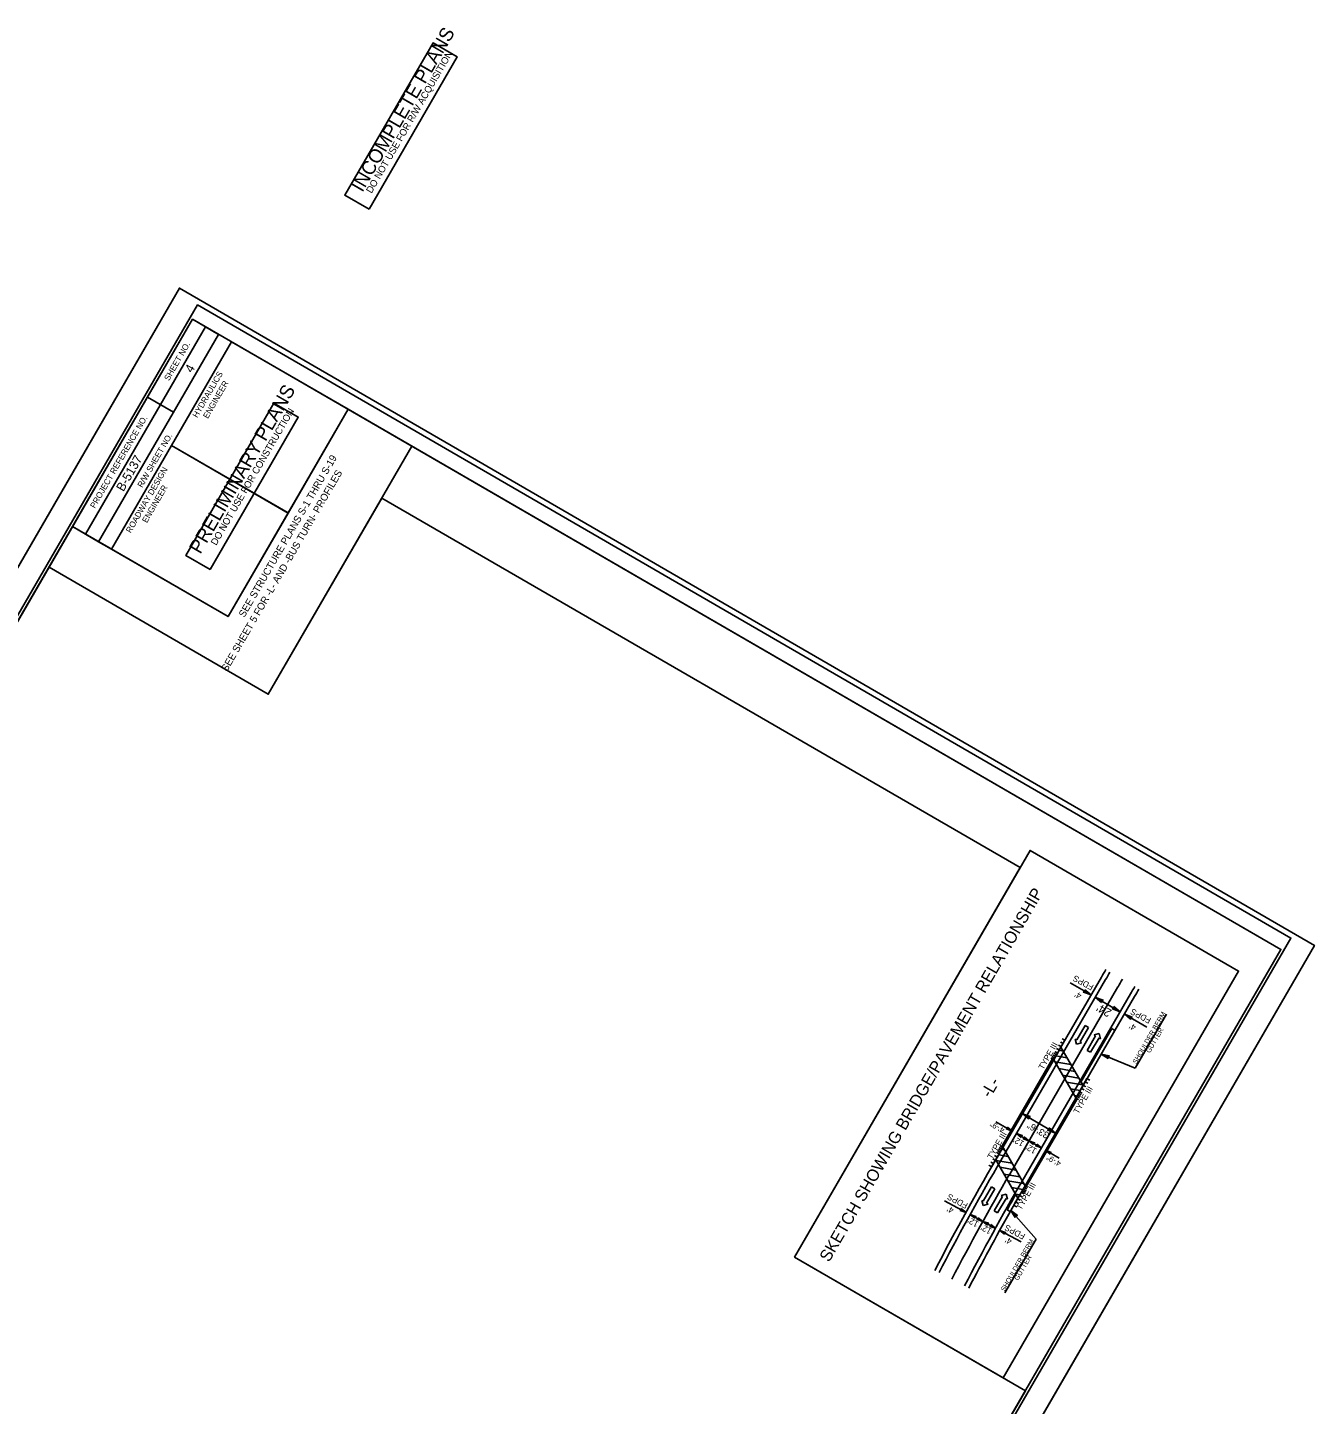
# Model space of a CAD drawing. Extents: x 1652765 to 1654556, y 596901 to 599124.
# Drawn here: x 1653481 to 1654556, y 597974 to 599124 of the extents above; entities that cross this region are included whole.
import ezdxf

# ---------------------------------------------------------------- set-up
doc = ezdxf.new("R2010")
doc.units = 0
for name, color, linetype in [('Prop Approach Slab', 7, 'Continuous'), ('Prop Approach Slab Hatching', 7, 'Continuous'), ('Prop Conc Shoulder Berm Gutter', 7, 'Continuous'), ('Prop Dimension Text', 7, 'Continuous'), ('Prop EOT', 7, 'Continuous'), ('Prop Horizontal Alignment', 7, 'Continuous'), ('Prop Horizontal Alignment Tick Label', 7, 'Continuous'), ('Prop Horizontal Alignment Tick Large', 7, 'Continuous'), ('Prop Horizontal Alignment Tick Small', 7, 'Continuous'), ('Prop Lane Arrow CELL', 7, 'Continuous'), ('Prop Paved Shoulder', 7, 'Continuous'), ('Prop Roadway Bridge', 7, 'Continuous'), ('Prop Structure Anchor Unit CELL', 7, 'Continuous'), ('Prop Terminator CELL', 7, 'Continuous'), ('Sheet Cutting Line CELL', 7, 'Continuous'), ('Sheet Plan Layout CELL', 7, 'Continuous'), ('Sheet Plot Border Inside CELL', 7, 'Continuous'), ('Sheet Sticker Incomplete CELL', 7, 'Continuous'), ('Sheet Sticker Preliminary CELL', 7, 'Continuous')]:
    doc.layers.add(name, color=color, linetype=linetype)

msp = doc.modelspace()

# ---------------------------------------------------------------- linework, layer by layer
at = {"layer": 'Prop Approach Slab'}
for p, q in [((1654338.2, 598262), (1654344.2, 598272.4)), ((1654362.7, 598240.4), (1654344.2, 598272.4)), ((1654356.6, 598230), (1654362.7, 598240.4)), ((1654289.8, 598178.5), (1654295.8, 598188.8)), ((1654289.8, 598178.5), (1654308.3, 598146.4)), ((1654308.3, 598146.4), (1654314.3, 598156.8))]:
    msp.add_line(p, q, dxfattribs=at)
at = {"layer": 'Prop Approach Slab Hatching'}
for p, q in [((1654342.7, 598269.9), (1654346, 598269.3)), ((1654339.2, 598260.4), (1654352.5, 598258)), ((1654340.1, 598265.3), (1654349.3, 598263.6)), ((1654342.4, 598254.7), (1654355.8, 598252.3)), ((1654345.7, 598249), (1654359, 598246.7)), ((1654348.9, 598243.4), (1654362.3, 598241)), ((1654352.2, 598237.7), (1654360.3, 598236.3)), ((1654355.5, 598232.1), (1654357.6, 598231.7)), ((1654294.9, 598187.3), (1654297, 598186.9)), ((1654290.1, 598178), (1654303.5, 598175.6)), ((1654292.3, 598182.7), (1654300.2, 598181.2)), ((1654293.4, 598172.3), (1654306.7, 598169.9)), ((1654296.6, 598166.6), (1654310, 598164.3)), ((1654299.9, 598161), (1654313.2, 598158.6)), ((1654303.1, 598155.3), (1654312.5, 598153.7)), ((1654306.4, 598149.7), (1654309.8, 598149.1))]:
    msp.add_line(p, q, dxfattribs=at)
at = {"layer": 'Prop Conc Shoulder Berm Gutter'}
for p, q in [((1654360.9, 598243.4), (1654386.7, 598288)), ((1654362.7, 598240.4), (1654389.3, 598286.5)), ((1654386.7, 598288), (1654389.3, 598286.5)), ((1654362.7, 598240.4), (1654360.9, 598243.4)), ((1654308.3, 598146.4), (1654306.6, 598149.4)), ((1654301.9, 598135.2), (1654299.3, 598136.6))]:
    msp.add_line(p, q, dxfattribs=at)
for radius, start in [(2257, 150.2578), (2254, 150.3017)]:
    msp.add_arc((1656266.2, 597029.7), radius, start, 150.6306, dxfattribs=at)
at = {"layer": 'Prop Dimension Text'}
for p, q in [((1654351.9, 598326.3), (1654369.5, 598316.1)), ((1654393.7, 598302.1), (1654373, 598314.1)), ((1654397.2, 598300.1), (1654416.1, 598289.1)), ((1654432.3, 598300.1), (1654406.1, 598254.9)), ((1654406.1, 598254.9), (1654377.9, 598266.7)), ((1654303.5, 598202.5), (1654290, 598210.3)), ((1654339.8, 598200.8), (1654312.1, 598216.9)), ((1654317.5, 598194.4), (1654307.1, 598200.4)), ((1654327.9, 598188.4), (1654317.5, 598194.4)), ((1654327.9, 598188.4), (1654327.9, 598188.4)), ((1654342.8, 598179.7), (1654331.4, 598186.4)), ((1654247.1, 598144.2), (1654265, 598134.6)), ((1654268.5, 598132.7), (1654279.1, 598127)), ((1654323.5, 598112.2), (1654302.5, 598136.2)), ((1654279.1, 598127), (1654289.7, 598121.4)), ((1654293.2, 598119.5), (1654311, 598109.9)), ((1654323.5, 598112.2), (1654297.5, 598067.3))]:
    msp.add_line(p, q, dxfattribs=at)
msp.add_lwpolyline([(1654121.9, 598097.2), (1654318.5, 598436.8), (1654492.6, 598336), (1654296, 597996.4)], close=True, dxfattribs=at)
at = {"layer": 'Prop EOT'}
for p, q in [((1654291.1, 598172.6), (1654381.5, 598329)), ((1654311.8, 598160.6), (1654402.3, 598317))]:
    msp.add_line(p, q, dxfattribs=at)
for centre, radius, start, end in [((1661316.3, 594316.3), 8012, 149.89309, 149.9451), ((1661316.3, 594316.3), 7988, 149.89416, 149.9451), ((1656266.2, 597029.7), 2282, 149.9451, 152.4748), ((1656266.2, 597029.7), 2258, 149.9451, 152.4748)]:
    msp.add_arc(centre, radius, start, end, dxfattribs=at)
at = {"layer": 'Prop Horizontal Alignment'}
msp.add_line((1654301.5, 598166.6), (1654391.9, 598323), dxfattribs=at)
msp.add_lwpolyline([(1652892.6, 597625.5), (1653801.3, 597099.3), (1654314.6, 597985.6), (1654121.9, 598097.2), (1654310.2, 598422.4), (1653777.2, 598731), (1653682.4, 598567.2), (1653499.4, 598673.2)], close=True, dxfattribs=at)
for centre, radius, start, end in [((1661316.3, 594316.3), 8000, 149.89309, 149.9451), ((1656266.2, 597029.7), 2270, 149.9451, 152.4748)]:
    msp.add_arc(centre, radius, start, end, dxfattribs=at)
at = {"layer": 'Prop Horizontal Alignment Tick Label'}
for p, q in [((1653529.9, 598700.9), (1653630.1, 598874)), ((1653540.7, 598694.6), (1653641, 598867.7)), ((1653540.7, 598694.6), (1653641, 598867.7)), ((1653581.7, 598815.3), (1653603.4, 598802.8)), ((1653601.7, 598774.9), (1653699, 598718.6)), ((1653540.7, 598694.6), (1653551.5, 598688.3))]:
    msp.add_line(p, q, dxfattribs=at)
for points in [[(1653619.3, 598880.3), (1652867.6, 597582.2), (1653776.2, 597056), (1654527.9, 598354.1)], [(1653519, 598707.2), (1653619.3, 598880.3), (1653641, 598867.7), (1653540.7, 598694.6)], [(1653601.7, 598774.9), (1653651.8, 598861.4), (1653749.1, 598805.1), (1653699, 598718.5)], [(1653776.2, 597056), (1652867.6, 597582.2), (1653519, 598707.2), (1653648.9, 598632), (1653749.1, 598805.1), (1654527.9, 598354.1)], [(1653551.5, 598688.3), (1653601.7, 598774.9), (1653699, 598718.5), (1653648.9, 598632)]]:
    msp.add_lwpolyline(points, close=True, dxfattribs=at)
at = {"layer": 'Prop Horizontal Alignment Tick Small'}
msp.add_lwpolyline([(1653712.3, 596900.7), (1654555.9, 598357.5), (1653608.3, 598906.3), (1652764.7, 597449.4)], close=True, dxfattribs=at)
at = {"layer": 'Prop Lane Arrow CELL'}
for p, q in [((1654357.4, 598278.6), (1654364.4, 598290.7)), ((1654364.4, 598290.7), (1654367.2, 598289)), ((1654357.3, 598275), (1654356.1, 598279.3)), ((1654356.1, 598279.3), (1654357.4, 598278.6)), ((1654367.2, 598289), (1654360.2, 598276.9)), ((1654366.2, 598269.8), (1654373.2, 598281.9)), ((1654376.1, 598280.3), (1654369, 598268.2)), ((1654371.9, 598282.7), (1654376.2, 598283.9)), ((1654373.2, 598281.9), (1654371.9, 598282.7)), ((1654377.3, 598279.5), (1654376.1, 598280.3)), ((1654376.2, 598283.9), (1654377.3, 598279.5)), ((1654361.5, 598276.1), (1654357.3, 598275)), ((1654360.2, 598276.9), (1654361.5, 598276.1)), ((1654369, 598268.2), (1654366.2, 598269.8)), ((1654279.4, 598143.8), (1654286.4, 598156)), ((1654289.2, 598154.3), (1654282.2, 598142.2)), ((1654286.4, 598156), (1654289.2, 598154.3)), ((1654279.3, 598140.3), (1654278.1, 598144.6)), ((1654278.1, 598144.6), (1654279.4, 598143.8)), ((1654283.5, 598141.4), (1654279.3, 598140.3)), ((1654282.2, 598142.2), (1654283.5, 598141.4)), ((1654288.6, 598135.8), (1654295.6, 598147.9)), ((1654298.4, 598146.2), (1654291.4, 598134.1)), ((1654294.3, 598148.6), (1654298.5, 598149.8)), ((1654295.6, 598147.9), (1654294.3, 598148.6)), ((1654299.7, 598145.5), (1654298.4, 598146.2)), ((1654298.5, 598149.8), (1654299.7, 598145.5)), ((1654291.4, 598134.1), (1654288.6, 598135.8))]:
    msp.add_line(p, q, dxfattribs=at)
at = {"layer": 'Prop Paved Shoulder'}
for p, q in [((1654344.2, 598272.4), (1654378.1, 598331)), ((1654389.3, 598286.5), (1654405.8, 598314.9))]:
    msp.add_line(p, q, dxfattribs=at)
for centre, radius, start, end in [((1661316.3, 594316.3), 8016, 149.89309, 149.9451), ((1661316.3, 594316.3), 7984, 149.89416, 149.9451), ((1656266.2, 597029.7), 2286, 149.6428, 152.4748), ((1656266.2, 597029.7), 2254, 150.6306, 152.4748)]:
    msp.add_arc(centre, radius, start, end, dxfattribs=at)
at = {"layer": 'Prop Roadway Bridge'}
for p, q in [((1654295.1, 598190.1), (1654337.5, 598263.3)), ((1654295.8, 598188.8), (1654338.2, 598262)), ((1654357.4, 598228.8), (1654337.5, 598263.3)), ((1654314.3, 598156.8), (1654356.6, 598230)), ((1654315, 598155.6), (1654357.4, 598228.8)), ((1654315, 598155.6), (1654295.1, 598190.1))]:
    msp.add_line(p, q, dxfattribs=at)
at = {"layer": 'Prop Structure Anchor Unit CELL'}
for p, q in [((1654345.6, 598278.8), (1654346.1, 598279.8)), ((1654347.6, 598278.3), (1654345.9, 598279.3)), ((1654338.2, 598262), (1654347.6, 598278.3)), ((1654338.5, 598266.6), (1654339.1, 598267.6)), ((1654340.5, 598266.1), (1654338.8, 598267.1)), ((1654339.3, 598268), (1654339.9, 598269)), ((1654341.3, 598267.5), (1654339.6, 598268.5)), ((1654340.9, 598270.7), (1654341.4, 598271.7)), ((1654342.9, 598270.2), (1654341.2, 598271.2)), ((1654342.4, 598273.4), (1654343, 598274.4)), ((1654344.5, 598272.9), (1654342.7, 598273.9)), ((1654344, 598276.1), (1654344.6, 598277.1)), ((1654346, 598275.6), (1654344.3, 598276.6)), ((1654336.2, 598262.6), (1654336.8, 598263.5)), ((1654338.2, 598262), (1654336.5, 598263)), ((1654337, 598263.9), (1654337.5, 598264.9)), ((1654339, 598263.4), (1654337.2, 598264.4)), ((1654337.7, 598265.3), (1654338.3, 598266.2)), ((1654339.8, 598264.8), (1654338, 598265.8)), ((1654356.6, 598230), (1654366, 598246.3)), ((1654366, 598246.3), (1654367.8, 598245.3)), ((1654367.5, 598244.8), (1654368, 598245.8)), ((1654358.2, 598232.7), (1654359.9, 598231.7)), ((1654359, 598234.1), (1654360.7, 598233.1)), ((1654359.8, 598235.4), (1654361.5, 598234.4)), ((1654360.4, 598232.6), (1654361, 598233.6)), ((1654361.2, 598233.9), (1654361.8, 598234.9)), ((1654361.3, 598238.1), (1654363.1, 598237.1)), ((1654362.8, 598236.6), (1654363.4, 598237.6)), ((1654362.9, 598240.9), (1654364.6, 598239.8)), ((1654364.3, 598239.4), (1654364.9, 598240.3)), ((1654364.5, 598243.6), (1654366.2, 598242.6)), ((1654365.9, 598242.1), (1654366.5, 598243)), ((1654356.6, 598230), (1654358.4, 598229)), ((1654357.4, 598231.4), (1654359.2, 598230.4)), ((1654358.1, 598228.5), (1654358.7, 598229.5)), ((1654358.9, 598229.9), (1654359.4, 598230.9)), ((1654359.7, 598231.2), (1654360.2, 598232.2)), ((1654295.8, 598188.8), (1654286.4, 598172.6)), ((1654292.8, 598187.6), (1654292.3, 598186.6)), ((1654294.3, 598186.1), (1654292.5, 598187.1)), ((1654293.6, 598189), (1654293, 598188)), ((1654295.1, 598187.5), (1654293.3, 598188.5)), ((1654294.4, 598190.3), (1654293.8, 598189.3)), ((1654295.8, 598188.8), (1654294.1, 598189.8)), ((1654286.6, 598176.8), (1654286, 598175.8)), ((1654288, 598175.3), (1654286.3, 598176.3)), ((1654288.1, 598179.5), (1654287.6, 598178.5)), ((1654289.6, 598178), (1654287.8, 598179)), ((1654289.7, 598182.2), (1654289.1, 598181.2)), ((1654291.1, 598180.7), (1654289.4, 598181.7)), ((1654291.3, 598184.9), (1654290.7, 598183.9)), ((1654292.7, 598183.4), (1654291, 598184.4)), ((1654292, 598186.3), (1654291.5, 598185.3)), ((1654293.5, 598184.8), (1654291.8, 598185.8)), ((1654285, 598174.1), (1654284.4, 598173.1)), ((1654286.4, 598172.6), (1654284.7, 598173.6)), ((1654314.3, 598156.8), (1654305, 598140.5)), ((1654312, 598152.8), (1654313.7, 598151.8)), ((1654312.7, 598154.1), (1654314.5, 598153.1)), ((1654314, 598152.3), (1654313.4, 598151.3)), ((1654313.5, 598155.5), (1654315.2, 598154.5)), ((1654314.8, 598153.6), (1654314.2, 598152.6)), ((1654314.3, 598156.8), (1654316, 598155.8)), ((1654315.5, 598155), (1654315, 598154)), ((1654316.3, 598156.3), (1654315.7, 598155.3)), ((1654305, 598140.5), (1654306.7, 598139.6)), ((1654306.5, 598143.3), (1654308.3, 598142.3)), ((1654308.5, 598142.8), (1654308, 598141.8)), ((1654308.1, 598146), (1654309.8, 598145)), ((1654310.1, 598145.5), (1654309.5, 598144.5)), ((1654309.6, 598148.7), (1654311.4, 598147.7)), ((1654311.6, 598148.2), (1654311.1, 598147.2)), ((1654311.2, 598151.4), (1654312.9, 598150.4)), ((1654313.2, 598150.9), (1654312.6, 598149.9)), ((1654307, 598140.1), (1654306.4, 598139.1))]:
    msp.add_line(p, q, dxfattribs=at)
at = {"layer": 'Prop Terminator CELL'}
for points in [[(1654364.2, 598320.5), (1654369.5, 598316.1), (1654363, 598318.5), (1654364.4, 598319.1)], [(1654378.2, 598309.7), (1654373, 598314.1), (1654379.5, 598311.8), (1654378.1, 598311.1)], [(1654388.5, 598306.5), (1654393.7, 598302.1), (1654387.2, 598304.5), (1654388.6, 598305.1)], [(1654402.4, 598295.7), (1654397.2, 598300.1), (1654403.7, 598297.7), (1654402.3, 598297.1)], [(1654383.7, 598263.1), (1654377.9, 598266.7), (1654384.6, 598265.2), (1654383.4, 598264.5)], [(1654317.3, 598212.5), (1654312.1, 598216.9), (1654318.5, 598214.5), (1654317.2, 598213.9)], [(1654299.6, 598205.7), (1654303.5, 598202.5), (1654298.8, 598204.2), (1654299.7, 598204.7)], [(1654311, 598197.2), (1654307.1, 598200.4), (1654311.9, 598198.7), (1654310.9, 598198.2)], [(1654334.5, 598205.2), (1654339.8, 598200.8), (1654333.3, 598203.2), (1654334.6, 598203.8)], [(1654313.7, 598197.6), (1654317.5, 598194.4), (1654312.8, 598196.1), (1654313.8, 598196.5)], [(1654321.4, 598191.2), (1654317.5, 598194.4), (1654322.2, 598192.7), (1654321.3, 598192.2)], [(1654324.1, 598191.6), (1654327.9, 598188.4), (1654323.2, 598190.1), (1654324.2, 598190.5)], [(1654335.2, 598183.2), (1654331.4, 598186.4), (1654336.1, 598184.6), (1654335.1, 598184.2)], [(1654261, 598137.7), (1654265, 598134.6), (1654260.2, 598136.1), (1654261.2, 598136.6)], [(1654272.4, 598129.6), (1654268.5, 598132.7), (1654273.3, 598131.1), (1654272.3, 598130.7)], [(1654275.1, 598130.1), (1654279.1, 598127), (1654274.3, 598128.6), (1654275.3, 598129.1)], [(1654306.1, 598130.4), (1654302.5, 598136.2), (1654307.9, 598131.9), (1654306.4, 598131.8)], [(1654283, 598124), (1654279.1, 598127), (1654283.9, 598125.5), (1654282.9, 598125)], [(1654285.7, 598124.4), (1654289.7, 598121.4), (1654284.9, 598122.9), (1654285.9, 598123.4)], [(1654297.1, 598116.4), (1654293.2, 598119.5), (1654298, 598117.9), (1654297, 598117.5)]]:
    msp.add_lwpolyline(points, close=True, dxfattribs=at)
at = {"layer": 'Sheet Cutting Line CELL'}
for p, q in [((1653608.3, 598906.3), (1652764.7, 597449.4)), ((1653712.3, 596900.7), (1654555.9, 598357.5))]:
    msp.add_line(p, q, dxfattribs=at)
at = {"layer": 'Sheet Plan Layout CELL'}
for points in [[(1653682.4, 598567.2), (1653802.3, 598774.3), (1653619.3, 598880.3), (1653499.4, 598673.2)], [(1652867.6, 597582.2), (1653776.2, 597056), (1654527.9, 598354.1), (1653802.3, 598774.3), (1653682.4, 598567.2), (1653499.4, 598673.2)]]:
    msp.add_lwpolyline(points, close=True, dxfattribs=at)
at = {"layer": 'Sheet Plot Border Inside CELL'}
msp.add_lwpolyline([(1653701.5, 596921.9), (1654536.3, 598363.6), (1653623.4, 598892.3), (1652788.5, 597450.6)], close=True, dxfattribs=at)
at = {"layer": 'Sheet Sticker Incomplete CELL'}
msp.add_lwpolyline([(1653766.6, 598972.1), (1653746.3, 598983.9), (1653820, 599111.1), (1653840.3, 599099.3)], close=True, dxfattribs=at)
at = {"layer": 'Sheet Sticker Preliminary CELL'}
msp.add_lwpolyline([(1653633.9, 598671.3), (1653613.5, 598683.1), (1653687.2, 598810.3), (1653707.5, 598798.6)], close=True, dxfattribs=at)

# ---------------------------------------------------------------- texts
at = {"layer": 'Prop Dimension Text'}
for s, height, rotation, p in [('SEE STRUCTURE PLANS S-1 THRU S-19', 6, 59.9255, (1653662.5, 598630.9)), ('SEE SHEET 5 FOR -L- AND -BUS TURN- PROFILES', 6, 59.9255, (1653648, 598585.6)), ('SKETCH SHOWING BRIDGE/PAVEMENT RELATIONSHIP', 10, 59.9255, (1654150.7, 598092.4)), ('FDPS', 5.1, 151.8546, (1654372.1, 598324.2)), ("4'", 5.1, 149.9255, (1654362, 598316.8)), ("24'", 7, 149.9255, (1654387.2, 598303.2)), ('FDPS', 5.1, 151.8546, (1654420.1, 598296.4)), ("4'", 5.1, 149.9255, (1654407.6, 598290.4)), ('SHOULDER BERM', 4.082, 59.9255, (1654407.3, 598258.1)), ('GUTTER', 4.08, 59.9255, (1654418.5, 598267.2)), ('-L-', 10, 59.9255, (1654285.3, 598229.5)), ('4\'-9"', 4.59, 149.9255, (1654297.7, 598204.5)), ('33\'-6"', 5.67, 149.9255, (1654334.9, 598200.7)), ("12'", 5.1, 149.9255, (1654314.1, 598193.4)), ("12'", 5.1, 149.9255, (1654324.5, 598187.4)), ('4\'-9"', 4.59, 149.9255, (1654344.9, 598176.6)), ('FDPS', 5.1, 151.8546, (1654267.1, 598141.8)), ("4'", 5.1, 151.8546, (1654255.4, 598137.8)), ("12'", 5.1, 151.8546, (1654276.1, 598126.4)), ("12'", 5.1, 151.8546, (1654287, 598120.5)), ('FDPS', 5.1, 151.8546, (1654315, 598116.1)), ('SHOULDER BERM', 4.082, 59.9255, (1654297.3, 598068.2)), ("4'", 5.1, 151.8546, (1654303.9, 598111.9)), ('GUTTER', 4.08, 59.9255, (1654308.5, 598077.3))]:
    msp.add_text(s, height=height, rotation=rotation, dxfattribs=at).set_placement(p)
at = {"layer": 'Prop Horizontal Alignment Tick Label'}
for s, p in [('SHEET NO.', (1653599.5, 598828.5)), ('HYDRAULICS', (1653623.2, 598797.6)), ('ENGINEER', (1653632, 598796.9)), ('PROJECT REFERENCE NO.', (1653537.7, 598722)), ('R/W SHEET NO.', (1653577.2, 598739.3)), ('ROADWAY DESIGN', (1653567.6, 598701.4)), ('ENGINEER', (1653581.1, 598709.8))]:
    msp.add_text(s, height=5, rotation=59.9255, dxfattribs=at).set_placement(p)
at = {"layer": 'Prop Horizontal Alignment Tick Large'}
for s, p in [('4', (1653618.8, 598835)), ('B-5137', (1653561.5, 598735.9))]:
    msp.add_text(s, height=7.5, rotation=59.9255, dxfattribs=at).set_placement(p)
at = {"layer": 'Prop Structure Anchor Unit CELL'}
for p in [(1654329.5, 598253.3), (1654358.7, 598216.4), (1654286.8, 598178.5), (1654311.1, 598136.1)]:
    msp.add_text('TYPE III', height=5, rotation=59.9255, dxfattribs=at).set_placement(p)
at = {"layer": 'Sheet Sticker Incomplete CELL'}
for s, height, p in [('INCOMPLETE PLANS', 11.52, (1653761, 598985.7)), ('DO NOT USE FOR R/W ACQUISITION', 5.76, (1653768.7, 598985))]:
    msp.add_text(s, height=height, rotation=59.9255, dxfattribs=at).set_placement(p)
at = {"layer": 'Sheet Sticker Preliminary CELL'}
for s, height, p in [('PRELIMINARY PLANS', 11.52, (1653625.7, 598683.6)), ('DO NOT USE FOR CONSTRUCTION', 5.76, (1653639, 598691))]:
    msp.add_text(s, height=height, rotation=59.9255, dxfattribs=at).set_placement(p)

doc.saveas('drawing.dxf')
